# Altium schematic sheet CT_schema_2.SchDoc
size 276 x 169 mm
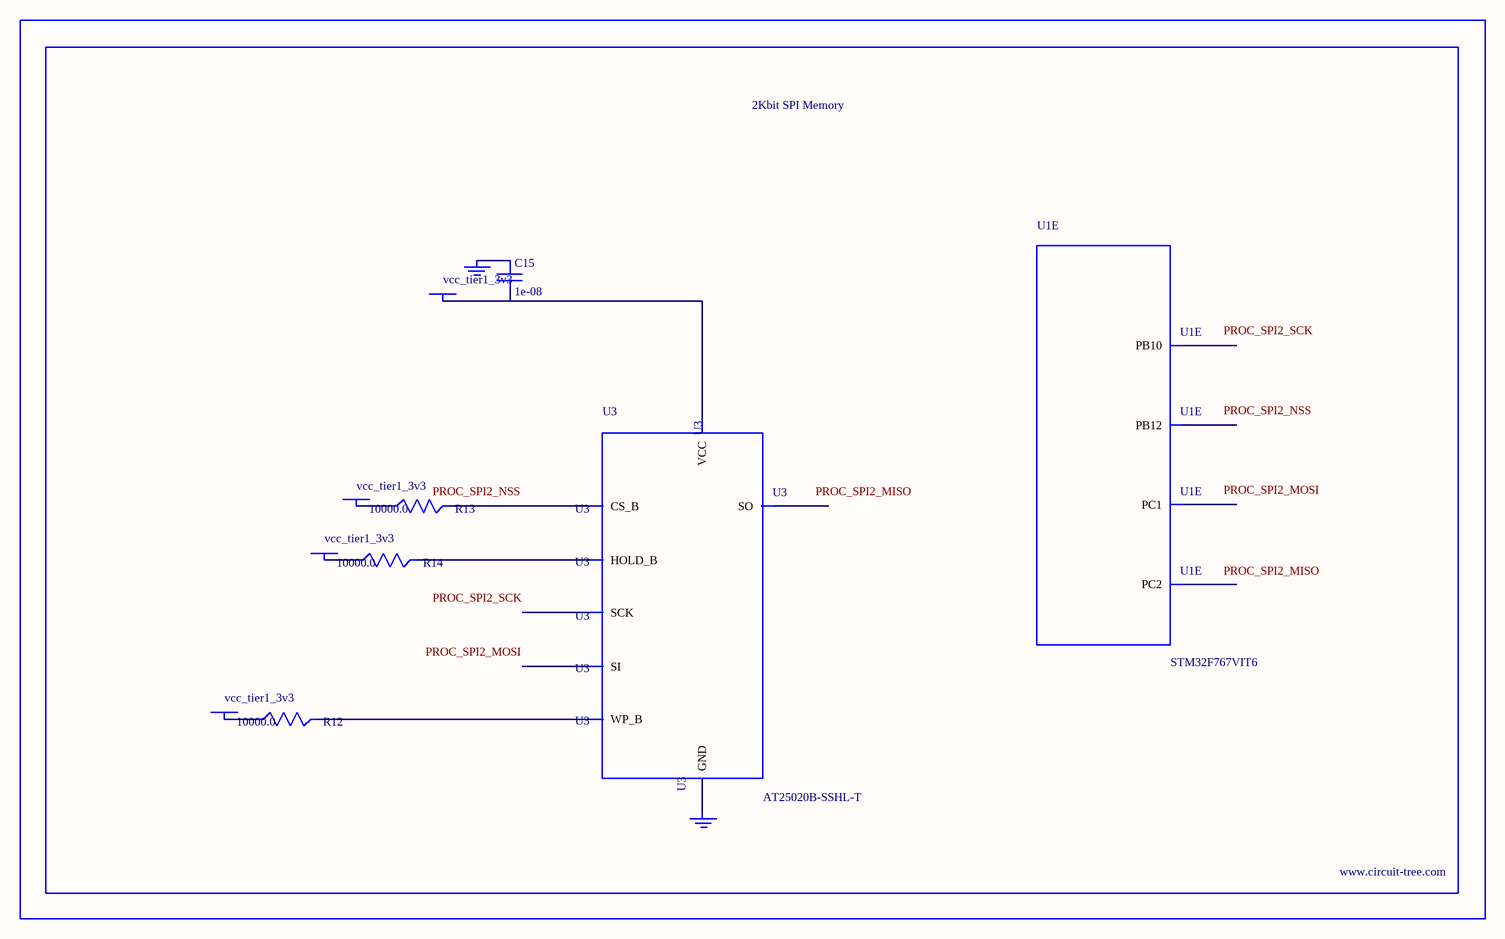
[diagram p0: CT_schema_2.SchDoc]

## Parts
BORDER1  (no value)
C15  1e-08  [C0402]
GND_INSTANCE_1_0  (no value)
GND_INSTANCE_1_1  (no value)
POWER_INSTANCE_1_0  vcc_tier1_3v3
POWER_INSTANCE_1_1  vcc_tier1_3v3
POWER_INSTANCE_1_2  vcc_tier1_3v3
POWER_INSTANCE_1_3  vcc_tier1_3v3
R12  10000.0  [R0603]
R13  10000.0  [R0603]
R14  10000.0  [R0603]
U1  STM32F767VIT6  [LQFP100]  (part E of 11)
U3  AT25020B-SSHL-T  [SOIC-8]

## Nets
NetC15_1: C15.1 GND_INSTANCE_1_0.0(GND)
NetC15_2: C15.2 POWER_INSTANCE_1_3.0(PWR) U3.8(VCC)
NetGND_INSTANCE_1_1_0: GND_INSTANCE_1_1.0(GND) U3.4(GND)
NetPOWER_INSTANCE_1_0_0: POWER_INSTANCE_1_0.0(PWR) R13.1
NetPOWER_INSTANCE_1_1_0: POWER_INSTANCE_1_1.0(PWR) R12.1
NetPOWER_INSTANCE_1_2_0: POWER_INSTANCE_1_2.0(PWR) R14.1
NetR12_2: R12.2 U3.3(WP_B)
NetR13_2: R13.2 U3.1(CS_B)
NetR14_2: R14.2 U3.7(HOLD_B)

Not connected (* = marked no-connect by the designer): U1 16(PC1) 17(PC2) 46(PB10) 51(PB12); U3 2(SO) 5(SI) 6(SCK)

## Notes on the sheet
- Labels drawn without touching a wire or pin: PROC_SPI2_MISO, PROC_SPI2_MOSI, PROC_SPI2_NSS, PROC_SPI2_SCK

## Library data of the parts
BORDER1 = BORDER_PAGE1
C15 = C0402C103K3RAC
GND_INSTANCE_1_0 GND_INSTANCE_1_1 = GND
POWER_INSTANCE_1_0-POWER_INSTANCE_1_3 = PWR
R12-R14 = RC0603JR-0710KL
